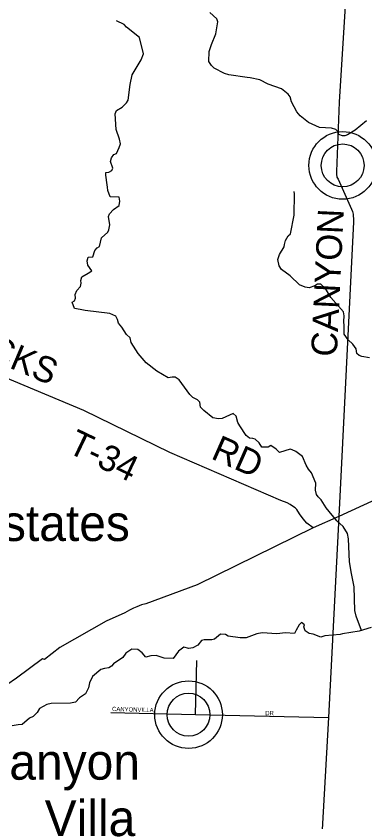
# Model space of a CAD drawing. Extents: x 0 to 40.4, y 0 to 22.
# Drawn here: x 4.998 to 5.767, y 17.952 to 19.724 of the extents above; entities that cross this region are included whole.
import ezdxf

# ---------------------------------------------------------------- set-up
doc = ezdxf.new("R2010")
doc.units = 0
for name, color, linetype in [('GM_X_Minor_River', 7, 'Continuous'), ('GM_X_Township_Road', 7, 'Continuous'), ('GM_X_Township_Road_Text', 7, 'Continuous'), ('GM_X_Township_Subdivision', 7, 'Continuous'), ('GM_X_Township_Subdivision_Text', 7, 'Continuous'), ('GM_X_Unincorporated', 7, 'Continuous'), ('GM_X_Unincorporated_Text', 7, 'Continuous')]:
    doc.layers.add(name, color=color, linetype=linetype)

msp = doc.modelspace()

# ---------------------------------------------------------------- linework, layer by layer
at = {"layer": 'GM_X_Minor_River'}
for points in [[(5.77, 19.4934), (5.7453, 19.4734), (5.7282, 19.4632), (5.7225, 19.461), (5.7172, 19.461), (5.7092, 19.4637), (5.7077, 19.4694), (5.7028, 19.4743), (5.693, 19.4774), (5.6668, 19.4794), (5.6426, 19.4901), (5.624, 19.5046), (5.6165, 19.5137), (5.6052, 19.5354), (5.6022, 19.5464), (5.5976, 19.5521), (5.5825, 19.5639), (5.5537, 19.5742), (5.5348, 19.5838), (5.5135, 19.5884), (5.5071, 19.5892), (5.4669, 19.5946), (5.457, 19.5977), (5.4347, 19.6092), (5.4287, 19.6153), (5.423, 19.6244), (5.4235, 19.6464), (5.4288, 19.6619), (5.4384, 19.6854), (5.4426, 19.7112), (5.4404, 19.718), (5.4253, 19.7321)], [(5.2113, 19.3896), (5.2064, 19.4044), (5.2083, 19.412), (5.2133, 19.42), (5.219, 19.4222), (5.2251, 19.4351), (5.2281, 19.4434), (5.2263, 19.4533), (5.2188, 19.4749), (5.2166, 19.5091), (5.2193, 19.5167), (5.2322, 19.5234), (5.2417, 19.5336), (5.2448, 19.5389), (5.2491, 19.5738), (5.2537, 19.5947), (5.2739, 19.6276), (5.2785, 19.6408), (5.2703, 19.6773), (5.2412, 19.6994), (5.2359, 19.7055), (5.2192, 19.7139)], [(5.7588, 18.3728), (5.747, 18.4043), (5.7443, 18.4164), (5.7426, 18.4684), (5.7374, 18.498), (5.733, 18.5234), (5.7301, 18.5742), (5.7282, 18.586), (5.7184, 18.6012), (5.7048, 18.6138), (5.6814, 18.6423), (5.6701, 18.6598), (5.6633, 18.6663), (5.6599, 18.672), (5.658, 18.6811), (5.6584, 18.697), (5.649, 18.7198), (5.6422, 18.7274), (5.6369, 18.7365), (5.6294, 18.7551), (5.6147, 18.7662), (5.6067, 18.77), (5.6018, 18.7715), (5.5782, 18.764), (5.5711, 18.7713), (5.5597, 18.7793), (5.5532, 18.7759), (5.5396, 18.7756), (5.5339, 18.7851), (5.5249, 18.7938), (5.5195, 18.795), (5.5127, 18.7954), (5.5052, 18.8018), (5.4908, 18.8228), (5.487, 18.8304), (5.4833, 18.8444), (5.4761, 18.8497), (5.4522, 18.8392), (5.4442, 18.8385), (5.4313, 18.8404), (5.4116, 18.8564), (5.4045, 18.864), (5.403, 18.875), (5.3977, 18.88), (5.3878, 18.885), (5.3807, 18.8918), (5.3572, 18.9237), (5.3489, 18.9298), (5.3421, 18.9302), (5.333, 18.9284), (5.3084, 18.9433), (5.2845, 18.9616), (5.2668, 18.9821), (5.2513, 19.0061), (5.2491, 19.0163), (5.2411, 19.0235), (5.2313, 19.0399), (5.2238, 19.0486), (5.2219, 19.0566), (5.2177, 19.0642), (5.2049, 19.0696), (5.1503, 19.0766), (5.1393, 19.0789), (5.1268, 19.0808), (5.1219, 19.0945), (5.1268, 19.0975), (5.1291, 19.104), (5.128, 19.1119), (5.1322, 19.1203), (5.1398, 19.1293), (5.1414, 19.1365), (5.1406, 19.1426), (5.1433, 19.1509), (5.157, 19.1589), (5.165, 19.1641), (5.1563, 19.1763), (5.1548, 19.1854), (5.1567, 19.1941), (5.1674, 19.1945), (5.1716, 19.2085), (5.1769, 19.2142), (5.1822, 19.2172), (5.1865, 19.2361), (5.2005, 19.249), (5.2028, 19.2539), (5.2044, 19.2653), (5.2014, 19.2835), (5.2041, 19.2892), (5.2125, 19.299), (5.225, 19.3077), (5.2266, 19.3171), (5.2251, 19.3259), (5.2054, 19.3267), (5.2001, 19.3407), (5.1994, 19.3476), (5.1986, 19.3529), (5.1957, 19.3741), (5.1961, 19.3802), (5.2021, 19.3806), (5.2094, 19.3843), (5.2113, 19.3896)], [(5.7766, 18.9723), (5.7595, 18.9754), (5.7542, 18.9773), (5.7489, 18.9819), (5.7471, 18.9921), (5.7399, 19.0028), (5.7297, 19.0119), (5.721, 19.0248), (5.7207, 19.043), (5.7203, 19.0521), (5.7208, 19.065), (5.7193, 19.0734), (5.6913, 19.105), (5.6796, 19.1251), (5.6694, 19.1342), (5.6618, 19.1343), (5.6565, 19.1309), (5.644, 19.1264), (5.6349, 19.1275), (5.6224, 19.1333), (5.602, 19.1527), (5.583, 19.1668), (5.5774, 19.1744), (5.5751, 19.1888), (5.5786, 19.1998), (5.5889, 19.2165), (5.5893, 19.2218), (5.5916, 19.2305), (5.5977, 19.2411), (5.6027, 19.2452), (5.6108, 19.2865), (5.6117, 19.3328), (5.6106, 19.3385)], [(5.7803, 18.3795), (5.7537, 18.3712), (5.7172, 18.3653), (5.7123, 18.3642), (5.6785, 18.3609), (5.6698, 18.3579), (5.6527, 18.3644), (5.644, 18.3659), (5.6349, 18.3721), (5.6323, 18.3804), (5.6335, 18.3853), (5.6267, 18.3899), (5.6221, 18.385), (5.6152, 18.3733), (5.6118, 18.3657), (5.5917, 18.3673), (5.5723, 18.3651), (5.5401, 18.3678), (5.5287, 18.3652), (5.5048, 18.3566), (5.4915, 18.3563), (5.4657, 18.3605), (5.4596, 18.3636), (5.4483, 18.3648), (5.4353, 18.3534), (5.4296, 18.3519), (5.4126, 18.3524), (5.4065, 18.3505), (5.3985, 18.3407), (5.3878, 18.3343), (5.3784, 18.3332), (5.3674, 18.3358), (5.3563, 18.3272), (5.3445, 18.3109), (5.324, 18.3117), (5.307, 18.3179), (5.2952, 18.3171), (5.2842, 18.3138), (5.2759, 18.3237), (5.2661, 18.3309), (5.2528, 18.3313), (5.2402, 18.3227), (5.233, 18.3136), (5.2128, 18.2992), (5.2087, 18.2943), (5.2026, 18.2906), (5.1931, 18.2887), (5.1847, 18.2868), (5.1668, 18.2717), (5.16, 18.2573), (5.1577, 18.2463), (5.1512, 18.2335), (5.1378, 18.2244), (5.1291, 18.215), (5.1181, 18.2127), (5.0752, 18.2117), (5.0661, 18.2095), (5.0494, 18.2008), (5.0444, 18.1925), (5.0357, 18.1834), (5.0277, 18.1797), (5.0113, 18.1661), (5.003, 18.165), (4.9893, 18.1628)]]:
    msp.add_lwpolyline(points, dxfattribs=at)
at = {"layer": 'GM_X_Township_Road'}
for points in [[(5.767, 20.1346), (5.7654, 20.1244), (5.7631, 20.1123), (5.7477, 19.9761), (5.7263, 19.788), (5.7255, 19.782), (5.7244, 19.771), (5.71, 19.5347), (5.7037, 19.3822), (5.704, 19.3765), (5.7051, 19.37), (5.7074, 19.3651), (5.7367, 19.2993), (5.739, 19.2944), (5.7405, 19.2887), (5.7409, 19.2849), (5.7412, 19.2784), (5.7412, 19.2712), (5.7095, 18.6233)], [(5.6523, 18.5981), (5.6383, 18.6088), (5.6308, 18.6183), (5.6228, 18.629), (5.6164, 18.6385), (5.613, 18.6427), (5.6073, 18.6461), (5.602, 18.6499), (5.5952, 18.6538), (5.5815, 18.6587), (5.3372, 18.7645), (5.1471, 18.8565), (4.9066, 18.9567), (4.7732, 19.0147)], [(6.1264, 18.8144), (5.7095, 18.6233), (5.6523, 18.5981), (5.3968, 18.4728), (5.2841, 18.4312), (5.2746, 18.429), (5.2643, 18.4248), (5.2567, 18.4218), (5.2483, 18.4173), (5.2376, 18.4113), (5.1965, 18.393), (5.0945, 18.335), (5.0605, 18.3088), (5.0561, 18.3105), (4.9987, 18.2677), (4.9774, 18.2534), (4.964, 18.2447), (4.9511, 18.238), (4.9366, 18.2319), (4.9183, 18.2252), (4.8769, 18.2146), (4.8363, 18.2023), (4.8029, 18.1929), (4.759, 18.178)], [(5.7095, 18.6233), (5.6866, 18.181), (5.6604, 17.7272)]]:
    msp.add_lwpolyline(points, dxfattribs=at)
at = {"layer": 'GM_X_Township_Subdivision'}
for points in [[(5.3937, 18.188), (5.3966, 18.307)], [(5.2068, 18.1925), (5.3937, 18.188), (5.6866, 18.181)]]:
    msp.add_lwpolyline(points, dxfattribs=at)
at = {"layer": 'GM_X_Unincorporated'}
for centre, radius in [((5.7176, 19.3957), 0.0744), ((5.7176, 19.3957), 0.0472), ((5.3781, 18.1875), 0.0744), ((5.3781, 18.1875), 0.0472)]:
    msp.add_circle(centre, radius, dxfattribs=at)

# ---------------------------------------------------------------- texts
at = {"layer": 'GM_X_Township_Road_Text'}
for s, rotation, p in [('CANYON', 87.2657, (5.7046, 18.974)), ('BLACKS', 336.915, (4.7986, 19.0291)), ('T-34', 334.3846, (5.1085, 18.7657)), ('RD', 336.0878, (5.4252, 18.7517))]:
    msp.add_text(s, height=0.05682, rotation=rotation, dxfattribs=at).set_placement(p)
at = {"layer": 'GM_X_Township_Subdivision_Text'}
for s, rotation, p in [('CANYONVILLA', 358.2995, (5.2095, 18.1955)), ('DR', 0, (5.547, 18.1864))]:
    msp.add_text(s, height=0.00947, rotation=rotation, dxfattribs=at).set_placement(p)
at = {"layer": 'GM_X_Unincorporated_Text'}
for s, height, p in [('Pinecrest Estates', 0.078977, (4.427, 18.5695)), ('Canyon', 0.07898, (4.907, 18.0445)), ('Villa', 0.07898, (5.0611, 17.9204))]:
    msp.add_text(s, height=height, rotation=0, dxfattribs=at).set_placement(p)

doc.saveas('drawing.dxf')
